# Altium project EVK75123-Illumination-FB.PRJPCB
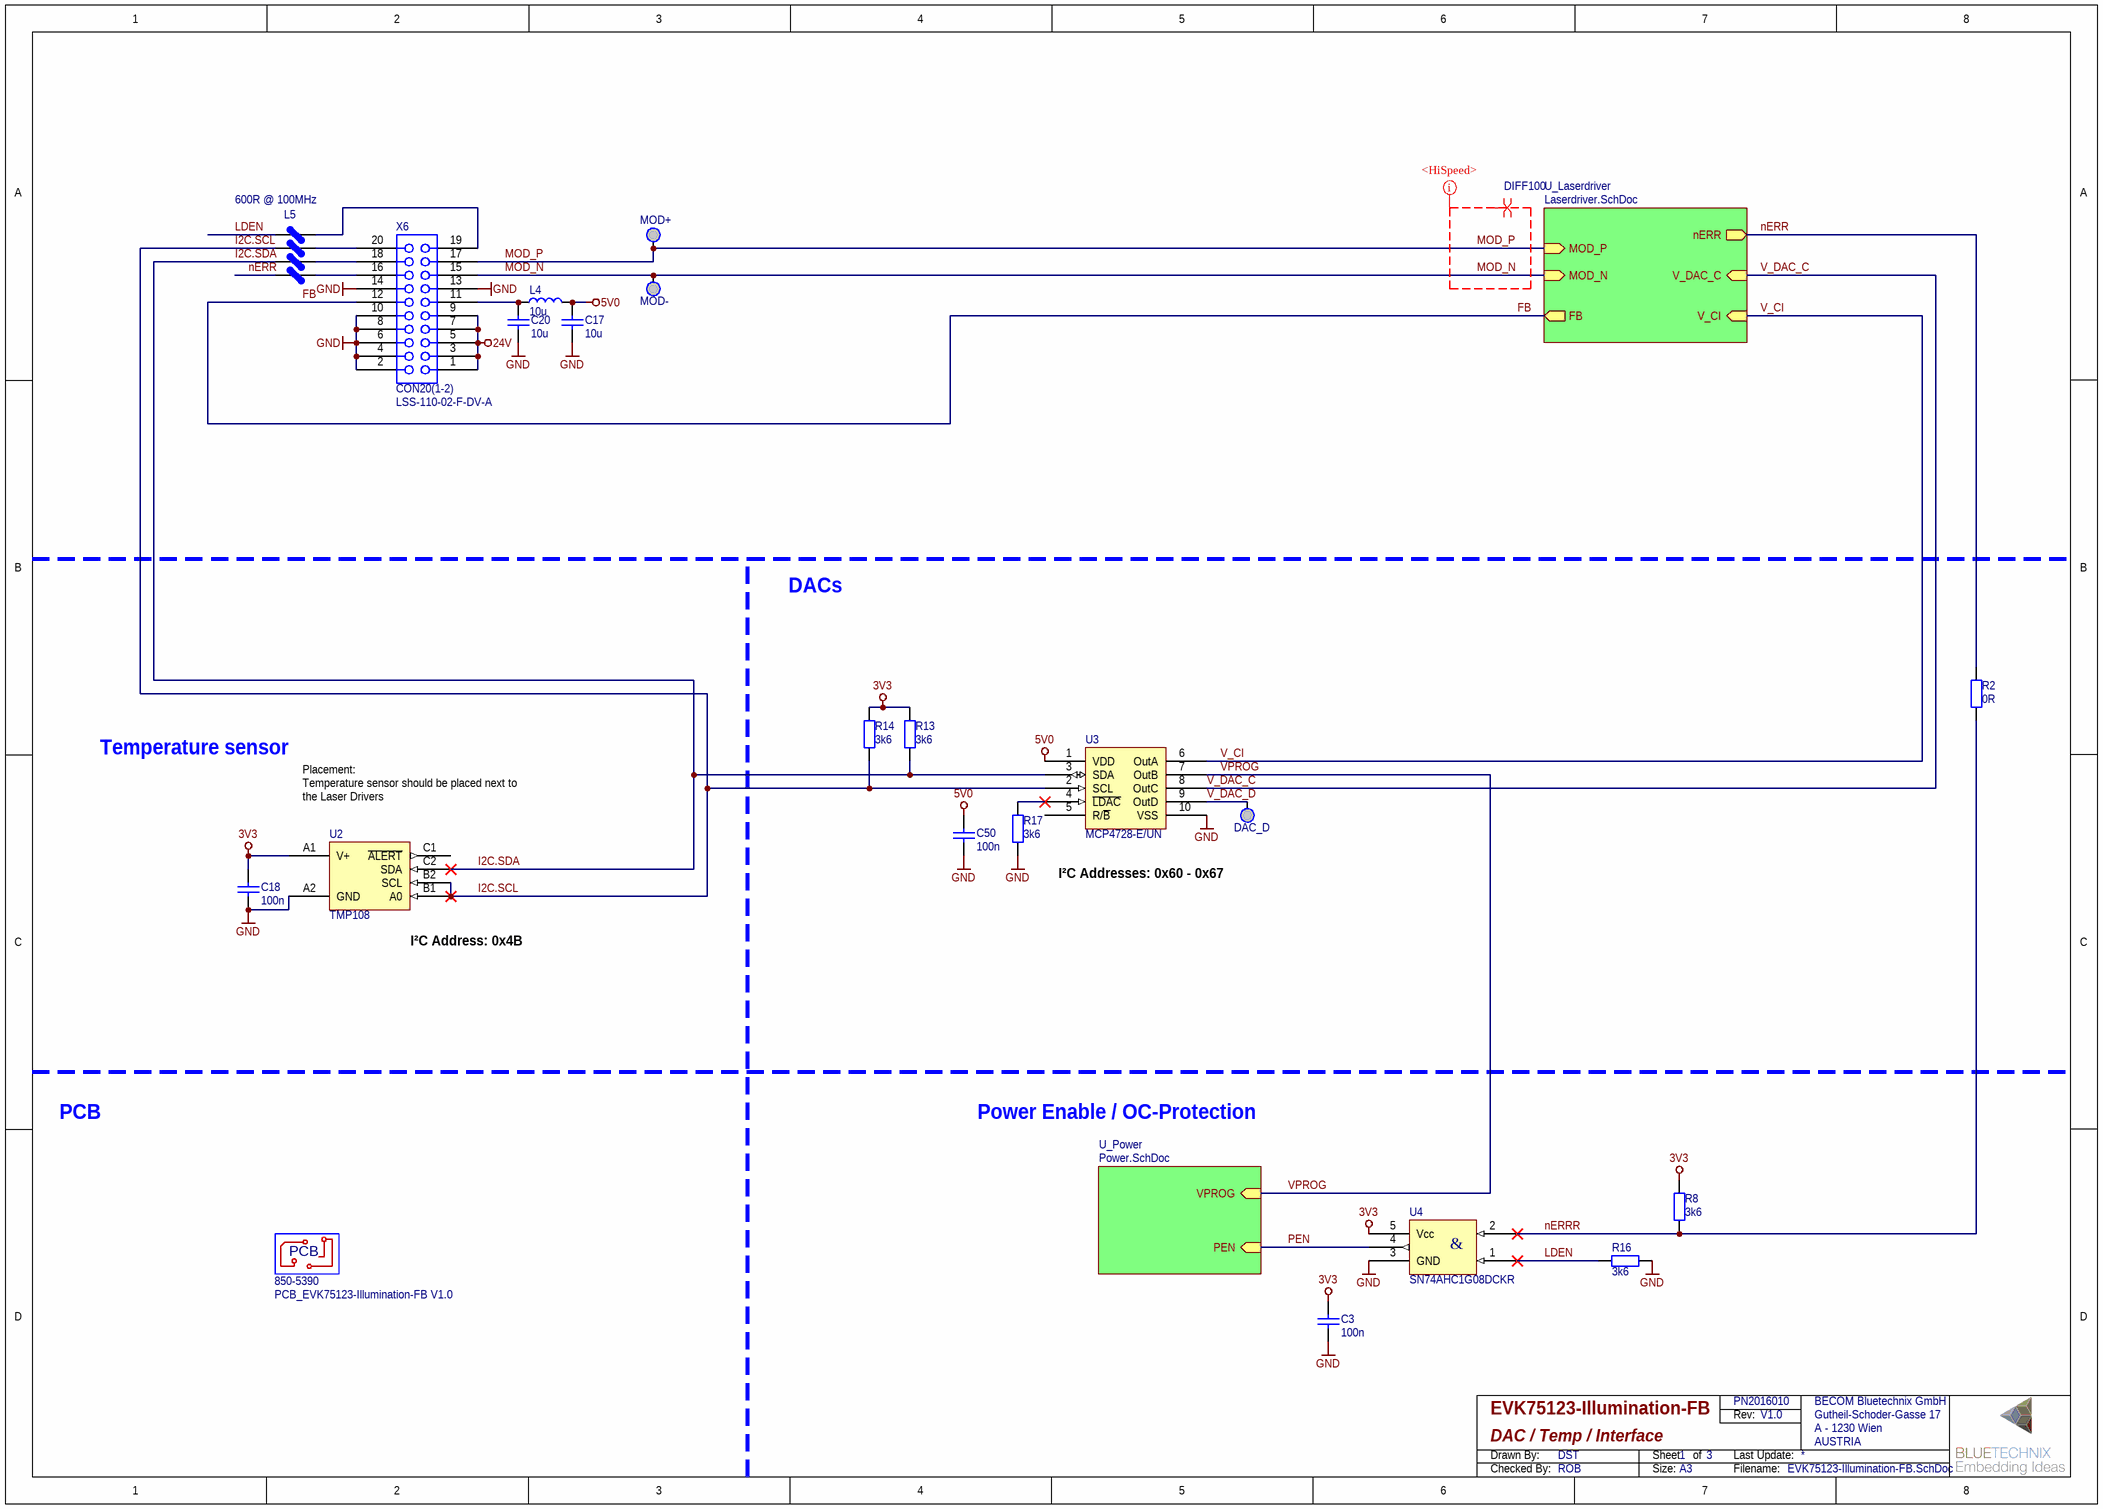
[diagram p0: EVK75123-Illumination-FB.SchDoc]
prj_name: EVK75123-Illumination-FB; prj_num: PN2016010; prj_vers: V1.0
3 sheets, 109 parts. Net scope: hierarchical (ports join the sheet entries above them; power ports are global).
Board file: EVK75123-Illumination-FB.PcbDoc
Sheets:
  EVK75123-Illumination-FB.SchDoc
    U_Power = Power.SchDoc
    U_Laserdriver = Laserdriver.SchDoc

## Sheet EVK75123-Illumination-FB.SchDoc: DAC / Temp / Interface
size A3; CheckedBy: ROB; DrawnBy: DST; Organization: BECOM Bluetechnix GmbH; Address1: Gutheil-Schoder-Gasse 17; Address2: A - 1230 Wien; Address3: AUSTRIA; DocumentNumber: 1; Revision: V1.0; SheetNumber: 1; SheetTotal: 3

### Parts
C3  C: 100n  [0402]  (hidden comment: Capacitor non-polarized)
C17  C: 10u  [0805]  (hidden comment: Capacitor non-polarized)
C18  C: 100n  [0402]  (hidden comment: Capacitor non-polarized)
C20  C: 10u  [0805]  (hidden comment: Capacitor non-polarized)
C50  C: 100n  [0402]  (hidden comment: Capacitor non-polarized)
DAC_D  Test Pad  [PAD_1mm_SMD]  (value not drawn)  (no BOM)
L4  L: 10u  [1210]  (hidden comment: Inductor)
L5  Z: 600R @ 100MHz  [1206_FB-array]  (hidden comment: Ferrite)
MOD+  Test Pad  [PAD_1mm_SMD]  (value not drawn)  (no BOM)
MOD-  Test Pad  [PAD_1mm_SMD]  (value not drawn)  (no BOM)
PCB  850-5390  [PCB]
R2  R: 0R  [0805]  (hidden comment: Resistor)
R8  R: 3k6  [0402]  (hidden comment: Resistor)
R13  R: 3k6  [0402]  (hidden comment: Resistor)
R14  R: 3k6  [0402]  (hidden comment: Resistor)
R16  R: 3k6  [0402]  (hidden comment: Resistor)
R17  R: 3k6  [0402]  (hidden comment: Resistor)
U2  TMP108  [BGA6-0.4-0.25-1.2x0.8]
U3  NAME: MCP4728-E/UN  [MSOP10-0.5-5]  (hidden comment: MCP4728)
U4  NAME: SN74AHC1G08DCKR  [SOT353-0.65--2.6]  (hidden comment: Single-Gate Dual-Input AND-Logic-Gate)
X6  CON20(1-2)  NAME: LSS-110-02-F-DV-A  [SAM-LSS-110-02-F-DV-A]

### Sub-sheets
U_Laserdriver = Laserdriver.SchDoc: MOD_P (in), MOD_N (in), nERR (out), V_CI (in), V_DAC_C (in), FB (out)
U_Power = Power.SchDoc: PEN (in), VPROG (in)

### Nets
3V3: C3.1 C18.2 R8.2 R13.2 R14.2 U2.A1(V+) U4.5(Vcc)
5V0: C17.2 C50.2 L4.2 U3.1(VDD)
24V: X6.1 X6.3 X6.5 X6.7 X6.9
GND: C3.2 C17.1 C18.1 C20.1 C50.1 R16.2 R17.1 U2.A2(GND) U3.10(VSS) U4.3(GND) X6.2 X6.4 X6.6 X6.8 X6.10 X6.13 X6.14
FB: X6.12 ; sheet U_Laserdriver/FB
I2C.SCL: L5.3 R14.1 U2.B1(A0) U2.B2(SCL) U3.2(SCL)
I2C.SDA: L5.2 R13.1 U2.C2(SDA) U3.3(SDA)
LDEN: L5.4 R16.1 U4.1(inB)
MOD_N: MOD-.1 X6.15 ; sheet U_Laserdriver/MOD_N
MOD_P: MOD+.1 X6.17 ; sheet U_Laserdriver/MOD_P
nERR: L5.1 R2.1 ; sheet U_Laserdriver/nERR
nERRR: R2.2 R8.1 U4.2(inA)
PEN: U4.4(out) ; sheet U_Power/PEN
V_CI: U3.6(OutA) ; sheet U_Laserdriver/V_CI
V_DAC_C: U3.8(OutC) ; sheet U_Laserdriver/V_DAC_C
V_DAC_D: DAC_D.1 U3.9(OutD)
VPROG: U3.7(OutB) ; sheet U_Power/VPROG
NetC20_2: C20.2 L4.1 X6.11
NetL5_5: L5.5 X6.19
NetL5_6: L5.6 X6.20
NetL5_7: L5.7 X6.18
NetL5_8: L5.8 X6.16
NetR17_2: R17.2 U3.4(~{LDAC})

Not connected (* = marked no-connect by the designer): U2 C1(~{ALERT}); U3 5(R/~{B})

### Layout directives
net class <HiSpeed>: MOD_N, MOD_P
differential pair; net class DIFF100: MOD_N, MOD_P

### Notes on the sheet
- DACs
- Temperature sensor
- Placement:
  Temperature sensor should be placed next to the Laser Drivers
- I²C Addresses: 0x60 - 0x67
- I²C Address: 0x4B
- PCB
- Power Enable / OC-Protection

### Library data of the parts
C3 = 54C877D5-E705-4C14-AD3D-8F4F7B57D597: C-0402-100n-16V-10%; Manufacturer: Murata; ArticleNumber: 710-0138; NAME: GRM155R71C104KA88D; Inventory Storage Name: LBaut; Inventory Storage Section: C3; Sachgruppe: Keramikscheiben; SachgruppeCode: C_KERAMIK; IsReviewed: 1; Dielektrikum: X7R; Montage: SMD; T-bereich: -55°C : +125°C; T_Koeffizient: ± 15%; Toleranz: 10%; U: 16V; InternalPrice: 0,011693; InternalStock: 600684
C17 C20 = 47BE2105-E645-4B7D-88B5-189FA600BE5F: C-0805-10u-10V-10%; Manufacturer: PhyComp; ArticleNumber: 710-0019; NAME: CC0805KKX5R6BB106; Inventory Storage Name: LBaut; Inventory Storage Section: C1; Sachgruppe: C_KERAMIK; SachgruppeCode: Keramikscheiben; IsReviewed: 1; InternalPrice: 0,285138; InternalStock: 500; U: 10V; Toleranz: 10%; Dielektrikum: X5R; T_Koeffizient: ± 15%; T-bereich: -55°C : +85°C; Montage: SMD
C18 = 54C877D5-E705-4C14-AD3D-8F4F7B57D597: C-0402-100n-16V-10%; Manufacturer: Murata; ArticleNumber: 710-0138; NAME: GRM155R71C104KA88D; Inventory Storage Name: LBaut; Inventory Storage Section: C3; Sachgruppe: Keramikscheiben; SachgruppeCode: C_KERAMIK; IsReviewed: 1; U: 16V; Toleranz: 10%; Dielektrikum: X7R; T_Koeffizient: ± 15%; T-bereich: -55°C : +125°C; Montage: SMD; InternalPrice: 0,013001; InternalStock: 607228
C50 = 54C877D5-E705-4C14-AD3D-8F4F7B57D597: C-0402-100n-16V-10%; Manufacturer: Murata; ArticleNumber: 710-0138; NAME: GRM155R71C104KA88D; Inventory Storage Name: LBaut; Inventory Storage Section: C3; Sachgruppe: Keramikscheiben; SachgruppeCode: C_KERAMIK; IsReviewed: 1; Dielektrikum: X7R; Montage: SMD; T-bereich: -55°C : +125°C; T_Koeffizient: ± 15%; Toleranz: 10%; U: 16V; InternalPrice: 0,013001; InternalStock: 607228
DAC_D MOD+ MOD- = D58E77CC-74E0-4972-9B60-0D1F1EE06ED8: Test Pad 1mm; Manufacturer: Bluetechnix; ArticleNumber: 810-0021; Inventory Storage Name: L2; SachgruppeCode: SV_TEST; IsReviewed: 1; InternalPrice: 0; Montage: THD
L4 = 5A39A3C7-8FFF-4AB6-80A4-55595FBEE935: L-1210-10u-450mA; Manufacturer: Murata; ArticleNumber: 770-0040; NAME: LQH32CN100K33L; Inventory Storage Name: LBaut; Inventory Storage Section: I4; Sachgruppe: IN_SPEICHERDROSSELN; SachgruppeCode: Speicherdrosseln; IsReviewed: 1; InternalPrice: 0,28; InternalStock: 400; Core: Ferrit; I: 0.45A; Toleranz: 10%; R_dc: 0R3; Q: 35; f_res: 26MHz; Schirm: n; Montage: SMD; T-bereich: -25°C : +85°C
L5 = 17bc767e-4081-41c9-96a1-8705f6a55660: F-1206array-600Z-100mA; Manufacturer: Taiyo Yuden; ArticleNumber: 740-0005; NAME: BK32164M601-T; Inventory Storage Name: LBaut; Inventory Storage Section: L1; Sachgruppe: FI_FERRITPERLEN; SachgruppeCode: Ferritperlen; IsReviewed: 1; InternalPrice: 0,09; InternalStock: 188; Wege: 4; R_dc: 0R6; Bandbreite: 250R @ 1GHz; Frequenz: 220MHz; I_max: 100mA; Bauform: 1206-array; Montage: SMD; T-bereich: -55°C : +125°C
PCB = 5ec15bad-9016-406e-8801-bfda4c5ae292: PCB_EVK75123-Illumination-FB V1.0; Manufacturer: Bluetechnix; Inventory Storage Name: L2; Sachgruppe: PCB_EXTPROJEKT; SachgruppeCode: externe Projekte; IsReviewed: 0; Kunde: Melexis
R2 = 96878DCE-2E24-48BD-A958-A9B2669E8EA5: R-0805-0R-5%; Manufacturer: YAGEO; ArticleNumber: 780-0259; NAME: RC0805JR-070RL; Inventory Storage Name: LBaut; Inventory Storage Section: R6; Sachgruppe: R_DICKSCHICHT; SachgruppeCode: Dickschicht; IsReviewed: 1; InternalPrice: 0,002857; InternalStock: 9206; P: 0.125W; Toleranz: 5%; T_Koeffizient: ± 250ppm/°C; Montage: SMD
R8 R13 R14 R16 R17 = 87ff11f6-a19c-4fd3-a86d-d729e9959c04: R-0402-3k6-1%; Manufacturer: MULTICOMP; ArticleNumber: 780-0477; NAME: MC 0.0625W 0402 1% 3K6; Inventory Storage Name: LBaut; Sachgruppe: Dickschicht; SachgruppeCode: R_DICKSCHICHT; IsReviewed: 1; InternalPrice: 0,040357; InternalStock: 256; P: 0.0625W; Toleranz: 1%; T_Koeffizient: ± 100ppm/°C; Montage: SMD; T-bereich: -55°C : +155°C; Inventory Storage Section: R10
U2 = 1756c951-2cf8-4c64-a988-e546f59afa21: ±1°C Accurate 12bit Digital Temperature Sensor; Manufacturer: Texas Instruments; ArticleNumber: 730-0256; Inventory Storage Name: L2; Sachgruppe: SENSOREN; IsReviewed: 0; Interface: SMBus/I2C; Messbereich: -40°C : +125°C; U: 1.4V : 3.6V; Bauform: WCSP6 (DSBGA-6); Montage: SMD; Kommentar: I²C: 0x70; PM: TA
U3 = 7021478d-2d84-431d-b8be-32d6dfcf2c4d: 12-Bit Digital-to-Analog Converter with EEPROM Memory; Manufacturer: Microchip; ArticleNumber: 700-1100; Inventory Storage Name: L2; Sachgruppe: IC_DATEN_SIGNALWANDLER; SachgruppeCode: Daten-/Signalwandler; IsReviewed: 0; Typ: DAC; Outputs: 4; Interface: I²C; U_IO: 2.7V : 5.5V; Aufloesung: 12bit; f_abtast: 166kHz; T-bereich: -40°C : +125°C; Bauform: MSOP10; Montage: SMD; topmark: 4728UN
U4 = B349E2D1-8349-4508-822A-E73FFBEB3634: 74AHC1G08; Manufacturer: Texas Instruments; ArticleNumber: 700-0623; Inventory Storage Name: LBaut; Inventory Storage Section: U20; Sachgruppe: Logic; SachgruppeCode: IC_LOGIC; IsReviewed: 1; InternalPrice: 0,06506; InternalStock: 172; Logik-Gruppe (NOR): AND; Logik-Typ (7402): 7408; Serie (HCT): AHC; Inputs: 2; Trigger: state; Out-Typ: TTL; t_t: 7ns; U: 2.0V : 5.5V; T-bereich: -40°C : +85°C; Bauform: SOT353-5; Montage: SMD; topmark: AE_
X6 = 379f8e5c-a288-4eeb-8f71-ca0e0501eadd: High speed hermaphrodotoc strip; Manufacturer: Samtec; ArticleNumber: 810-0543; Inventory Storage Name: LBaut; Inventory Storage Section: X23; Sachgruppe: Mezzanin; SachgruppeCode: SV_MEZZANIN; IsReviewed: 1; InternalPrice: 0,853333; InternalStock: 60; Typ: B2B; Pole: 20; Gender: h; Winkel: 180°; Reihen: 2; Pitch: 0.635mm; I_max: 1.7A; Montage: SMD; Kommentar: hermaphroditic 7.49mm; T-bereich: -55°C : +125°C

## Sheet Power.SchDoc: Power
size A4; CheckedBy: ROB; DrawnBy: DST; Organization: BECOM Bluetechnix GmbH; Address1: Gutheil-Schoder-Gasse 17; Address2: A - 1230 Wien; Address3: AUSTRIA; DocumentNumber: 3; Revision: V1.0; SheetNumber: 3; SheetTotal: 3
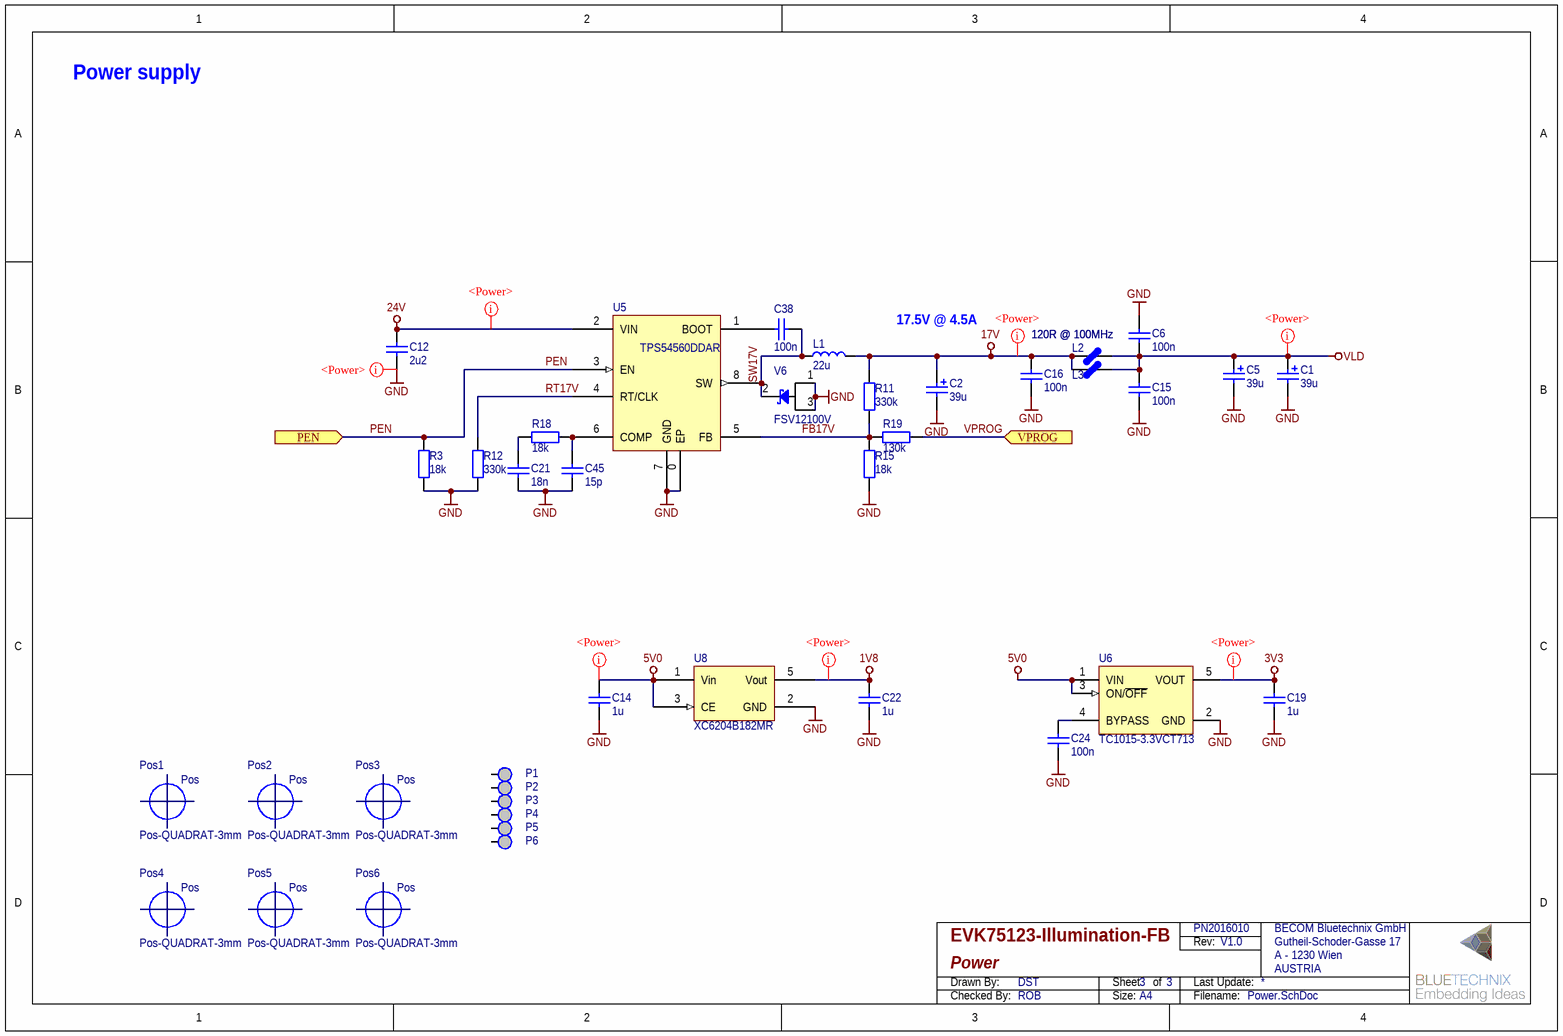
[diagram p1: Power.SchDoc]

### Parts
C1  C: 39u  [ELKO_SMD-8x7]  (hidden comment: Polarized Capicator)
C2  C: 39u  [ELKO_SMD-8x7]  (hidden comment: Polarized Capicator)
C5  C: 39u  [ELKO_SMD-8x7]  (hidden comment: Polarized Capicator)
C6  C: 100n  [1206]  (hidden comment: Capacitor non-polarized)
C12  C: 2u2  [1210]  (hidden comment: Capacitor non-polarized)
C14  C: 1u  [0603]  (hidden comment: Capacitor non-polarized)
C15  C: 100n  [1206]  (hidden comment: Capacitor non-polarized)
C16  C: 100n  [0603]  (hidden comment: Capacitor non-polarized)
C19  C: 1u  [0603]  (hidden comment: Capacitor non-polarized)
C21  C: 18n  [0402]  (hidden comment: Capacitor non-polarized)
C22  C: 1u  [0603]  (hidden comment: Capacitor non-polarized)
C24  C: 100n  [0603]  (hidden comment: Capacitor non-polarized)
C38  C: 100n  [0603]  (hidden comment: Capacitor non-polarized)
C45  C: 15p  [0402]  (hidden comment: Capacitor non-polarized)
L1  L: 22u  [VIS-IHLP-6767DZ]  (hidden comment: Inductor)
L2  Z: 120R @ 100MHz  [0805]  (hidden comment: Ferrite)
L3  Z: 120R @ 100MHz  [0805]  (hidden comment: Ferrite)
P1  Test Pad  [PAD_M2-5x5]  (value not drawn)  (no BOM)
P2  Test Pad  [PAD_M2-5x5]  (value not drawn)  (no BOM)
P3  Test Pad  [PAD_M2-5x5]  (value not drawn)  (no BOM)
P4  Test Pad  [PAD_M2-5x5]  (value not drawn)  (no BOM)
P5  Test Pad  [PAD_M2-5x5]  (value not drawn)  (no BOM)
P6  Test Pad  [PAD_M2-5x5]  (value not drawn)  (no BOM)
Pos1  Position  [Pos-QUADRAT]  (value not drawn)
Pos2  Position  [Pos-QUADRAT]  (value not drawn)
Pos3  Position  [Pos-QUADRAT]  (value not drawn)
Pos4  Position  [Pos-QUADRAT]  (value not drawn)
Pos5  Position  [Pos-QUADRAT]  (value not drawn)
Pos6  Position  [Pos-QUADRAT]  (value not drawn)
R3  R: 18k  [0402]  (hidden comment: Resistor)
R11  R: 330k  [0402]  (hidden comment: Resistor)
R12  R: 330k  [0402]  (hidden comment: Resistor)
R15  R: 18k  [0402]  (hidden comment: Resistor)
R18  R: 18k  [0402]  (hidden comment: Resistor)
R19  R: 130k  [0402]  (hidden comment: Resistor)
U5  NAME: TPS54560DDAR  [PSO8-1.27-7.3]  (hidden comment: TPS54061)
U6  NAME: TC1015-3.3VCT713  [SOT23-5-0.95--3.6]  (hidden comment: LP2985)
U8  NAME: XC6204B182MR  [SOT23-5-0.95--3.6]  (hidden comment: High-Speed LDO Voltage-Regulator)
V6  NAME: FSV12100V  [TO-277-3]  (hidden comment: Default Diode)

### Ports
PEN (in), VPROG (in)

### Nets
1V8: C22.2 U8.5(Vout)
3V3: C19.2 U6.5(VOUT)
5V0: C14.2 U6.1(VIN) U6.3(ON/~{OFF}) U8.1(Vin) U8.3(CE)
17V: C2.1 C16.1 L1.2 L2.1 L3.1 R11.1
24V: C12.2 U5.2(VIN)
GND: C1.2 C2.2 C5.2 C6.2 C12.1 C14.1 C15.1 C16.2 C19.1 C21.1 C22.1 C24.2 C45.1 R3.1 R12.2 R15.1 U5.0(EP) U5.7(GND) U6.2(GND) U8.2(GND) V6.1(A) V6.3(A)
VLD: C1.1 C5.1 C6.1 C15.2 L2.2 L3.2
FB17V: R11.2 R15.2 R19.1 U5.5(FB)
PEN: R3.2 U5.3(EN) ; port PEN
RT17V: R12.1 U5.4(RT/CLK)
SW17V: C38.1 L1.1 U5.8(SW) V6.2(K)
VPROG: R19.2 ; port VPROG
NetC21_2: C21.2 R18.2
NetC24_1: C24.1 U6.4(BYPASS)
NetC38_2: C38.2 U5.1(BOOT)
NetC45_2: C45.2 R18.1 U5.6(COMP)

Not connected (* = marked no-connect by the designer): P1 1; P2 1; P3 1; P4 1; P5 1; P6 1

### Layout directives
net class <Power>: 1V8, 3V3, 5V0, 17V, 24V, GND, VLD

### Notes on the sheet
- Power supply
- 17.5V @ 4.5A

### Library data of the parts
C1 C2 C5 = 44276342-0de9-47a7-a7a6-11334c4a2d95: C-39u-35V-20%-30mR; Manufacturer: Panasonic; ArticleNumber: 710-0385; NAME: 35SVPF39M; Inventory Storage Name: LBaut; Inventory Storage Section: C7; Sachgruppe: C_ALUMINIUM_ELKO; SachgruppeCode: Aluminium Elektrolyt; IsReviewed: 0; InternalPrice: 0,417272; InternalStock: 8; U: 35V; Toleranz: 20%; ESR: 30mR; Z: 30mR @ 100kHz; T-bereich: -55°C : +105°C; Lebensdauer: 5000h @ 105°C; Bauform: 8.3x8.3x6.9; Montage: SMD; Kommentar: Irip=2.8A
C6 C15 = 6574bd8d-1f7f-4017-8c13-fc1ff6c564f2: C-1206-100n-50V-5%; Manufacturer: TDK; ArticleNumber: 710-0354; NAME: CGA5L2C0G1H104J160AA; Inventory Storage Name: L2; Sachgruppe: C_KERAMIK; SachgruppeCode: Keramikscheiben; IsReviewed: 1; InternalPrice: 0; InternalStock: 12; U: 50V; Toleranz: 5%; Dielektrikum: C0G; T-bereich: -55°C : +125°C; Montage: SMD
C12 = c11633e3-883f-4ea1-bab5-305a930c1712: C-1210-2u2-100V-X7R; Manufacturer: Kemet; ArticleNumber: 710-0311; NAME: C1210C225K1RACTU; Inventory Storage Name: LBaut; Inventory Storage Section: C6; Sachgruppe: C_KERAMIK; SachgruppeCode: Keramikscheiben; IsReviewed: 1; InternalPrice: 0,24625; InternalStock: 20; U: 100V; Toleranz: 10%; Dielektrikum: X7R; T_Koeffizient: ± 15%; T-bereich: -55°C : +125°C; Montage: SMD
C14 C19 C22 = 62C539F0-6F12-4C64-8973-B77ABBA35E0D: C-0603-1u-25V-10%; Manufacturer: Kemet; ArticleNumber: 710-0184; NAME: C0603C105K3PACTU; Inventory Storage Name: LBaut; Inventory Storage Section: C4; Sachgruppe: C_KERAMIK; SachgruppeCode: Keramikscheiben; IsReviewed: 1; InternalPrice: 0,009729; InternalStock: 756; U: 25V; Toleranz: 10%; Dielektrikum: X5R; T_Koeffizient: ± 15%; T-bereich: -55°C : +85°C; Montage: SMD
C16 C24 C38 = F4F417EB-80BB-43BD-9294-E69FEC10CC02: C-0603-100n-50V-10%; Manufacturer: MULTICOMP; ArticleNumber: 710-0283; NAME: MCCA000255; Inventory Storage Name: LBaut; Inventory Storage Section: C6; Sachgruppe: Keramikscheiben; SachgruppeCode: C_KERAMIK; IsReviewed: 1; InternalPrice: 0,01; InternalStock: 1912; U: 50V; Toleranz: 10%; Dielektrikum: X7R; T_Koeffizient: ± 15%; T-bereich: -55°C : +125°C; Montage: SMD
C21 = 0D03DA8E-6E9D-48FA-B2D5-DDC88D2A4CF2: C-0402-18n-16V-10%; Manufacturer: AVX; ArticleNumber: 710-0219; NAME: 0402YC183KAT2A; Inventory Storage Name: LBaut; Inventory Storage Section: C5; Sachgruppe: C_KERAMIK; SachgruppeCode: Keramikscheiben; IsReviewed: 1; InternalPrice: 0; U: 16V; Toleranz: 10%; Dielektrikum: X7R; T_Koeffizient: ±15%; T-bereich: -55°C : +125°C; Montage: SMD
C45 = 11FE33DF-B8B2-497C-ADE2-798944BCF4BE: C-0402-15p-50V-5%; Manufacturer: PhyComp; ArticleNumber: 710-0115; NAME: CC0402JRNPO9BN150; Inventory Storage Name: LBaut; Inventory Storage Section: C3; Sachgruppe: C_KERAMIK; SachgruppeCode: Keramikscheiben; IsReviewed: 1; InternalPrice: 0,009; InternalStock: 288; U: 50V; Toleranz: 5%; Dielektrikum: C0G; T_Koeffizient: ± 15%; T-bereich: -55°C : +125°C; Montage: SMD
L1 = c927bdf3-e195-4335-ae34-2dcccbc64859: L-VIS-IHLP-6767-22u-6.2A-20%; Manufacturer: Vishay; ArticleNumber: 770-0190; NAME: IHLP6767DZER220M11; Inventory Storage Name: L2; Sachgruppe: IN_SPEICHERDROSSELN; SachgruppeCode: Speicherdrosseln; IsReviewed: 0; I: 7.2A; I_sat: 6.2A; Toleranz: 20%; R_dc: 0R043; f_res: 5MHz; Schirm: y; Bauform: 17 x 17 x 4 mm; Montage: SMD; T-bereich: -55°C : +155°C
L2 L3 = 4558f3ef-a2ca-4732-a97e-33e36c5aad12: F-0805-120Z-5A; Manufacturer: MEC MARCOM; ArticleNumber: 740-0008; NAME: MLB-201209-0120PU; Inventory Storage Name: LBaut; Inventory Storage Section: L2; Sachgruppe: FI_FERRITPERLEN; SachgruppeCode: Ferritperlen; IsReviewed: 1; InternalPrice: 0,068522; InternalStock: 84; R_dc: 0R02; Bandbreite: 110R @ 1GHz; Frequenz: 300MHz; I_max: 5A; Montage: SMD; T-bereich: -55°C : +125°C
P1-P6 = d95d2f47-965b-47b2-ac00-e8d5b9325de3: M2 Mounting Hole 5x5; Manufacturer: Bluetechnix; ArticleNumber: 810-0545; Inventory Storage Name: L2; SachgruppeCode: SV_TEST; IsReviewed: 1; InternalPrice: 0; Typ: Mount Hole
Pos1-Pos6 = A97550DC-E5EA-465D-9168-34E3565B8720: Pos-QUADRAT-3mm; Manufacturer: Bluetechnix; MountOption: DNP; ArticleNumber: 880-0007; Inventory Storage Name: L2; Sachgruppe: PCB-Symbole; SachgruppeCode: DIV_SYMBOLE; IsReviewed: 1; Groesse: 3mm; InternalPrice: 0
R3 R15 = A4A7BB00-465D-4C1E-8319-4836672F5686: R-0402-18k-1%; Manufacturer: YAGEO; ArticleNumber: 780-0108; NAME: RC0402FR-0718KL; Inventory Storage Name: LBaut; Inventory Storage Section: R3; Sachgruppe: R_DICKSCHICHT; SachgruppeCode: Dickschicht; IsReviewed: 1; InternalPrice: 0,009565; InternalStock: 808; P: 0.063W; Toleranz: 1%; T_Koeffizient: ± 250ppm/°C; Montage: SMD; T-bereich: -55°C : +155°C
R11 R12 = 0499915E-9BF4-4C7F-8B08-D182950F3B89: R-0402-330k-1%; Manufacturer: YAGEO; ArticleNumber: 780-0326; NAME: RC0402FR-07330KL; Inventory Storage Name: LBaut; Inventory Storage Section: R7; Sachgruppe: R_DICKSCHICHT; SachgruppeCode: Dickschicht; IsReviewed: 1; InternalPrice: 0,01625; InternalStock: 86; P: 0.063W; Toleranz: 1%; T_Koeffizient: ± 250ppm/°C; Montage: SMD; T-bereich: -55°C : +155°C
R18 = A4A7BB00-465D-4C1E-8319-4836672F5686: R-0402-18k-1%; Manufacturer: YAGEO; ArticleNumber: 780-0108; NAME: RC0402FR-0718KL; Inventory Storage Name: LBaut; Inventory Storage Section: R3; Sachgruppe: R_DICKSCHICHT; SachgruppeCode: Dickschicht; IsReviewed: 1; InternalPrice: 0,00923; InternalStock: 972; P: 0.063W; Toleranz: 1%; T_Koeffizient: ± 250ppm/°C; Montage: SMD; T-bereich: -55°C : +155°C
R19 = 57b0607b-283e-4831-8b97-1b038861c010: R-0402-130k-1%; Manufacturer: Multcomp; ArticleNumber: 780-0509; NAME: MCMR04X1303FTL; Inventory Storage Name: LBaut; Inventory Storage Section: R11; Sachgruppe: R_DICKSCHICHT; SachgruppeCode: Dickschicht; IsReviewed: 1; InternalPrice: 0,001481; InternalStock: 122; P: 0.063W; Toleranz: 1%; T_Koeffizient: ± 100ppm/°C; Montage: SMD; T-bereich: -55°C : +125°C
U5 = 83e8cd34-1e26-4937-9357-3a852f02699a: 4.5 V to 60 V Input, 5 A, Step Down DC-DC Converter with Eco-mode; Manufacturer: Texas Instruments; ArticleNumber: 700-1098; Inventory Storage Name: LBaut; Inventory Storage Section: U48; Sachgruppe: PM_BUCK; SachgruppeCode: Buck; IsReviewed: 0; InternalPrice: 2,225; InternalStock: 2; U_in(max): 60V; U_in(min): 4.5V; U_out(max): 58.8V; U_out(min): 0.8V; fix_var: var; I_out: 5A; T-bereich: -40°C : +150°C; Bauform: HSOP8; Montage: SMD; Frequenz: 100kHz : 2.5MHz
U6 = 595174d6-4f0f-4a85-858e-941119242838: 3.3V, Micropower 100 mA Low-Noise Ultra Low-Dropout Regulator; Manufacturer: Microchip Technology; ArticleNumber: 700-0834; Inventory Storage Name: LBaut; Inventory Storage Section: U31; Sachgruppe: PM_LINEAR; SachgruppeCode: Linear; IsReviewed: 1; InternalPrice: 0,255; InternalStock: 136; Typ: 3V3 LDO; U_in(max): 6V; U_in(min): 2.7V; fix_var: fix; I_out: 100mA; U_drop_out: 180mV; T-bereich: -40°C : +125°C; Bauform: SOT235; Montage: SMD; topmark: TC1015
U8 = 70773BAF-7633-4D88-81D5-082B1EC5F3A9: XC6204B-1V8; Manufacturer: Torex; ArticleNumber: 700-0025; Inventory Storage Name: LBaut; Inventory Storage Section: U2; Sachgruppe: PM_LINEAR; SachgruppeCode: Linear; IsReviewed: 1; InternalPrice: 0,394782; InternalStock: 182; U_in(max): 10V; U_in(min): 2.8V; U_out(max): 1.8V; fix_var: fix; I_out: 150mA; U_drop_out: 200mV; T-bereich: -40°C : 85°C; Bauform: SOT23-5; Montage: SMD
V6 = a2494603-b754-4332-b2d6-676b3f1482f6: 12A, 100V Ultra-Low Vf Schottky Rectifier; Manufacturer: Fairchild; ArticleNumber: 730-0269; Inventory Storage Name: LBaut; Sachgruppe: SE_SCHOTTKY; IsReviewed: 1; U_f: 483mV @ 5A, 25°C; I_f(max): 220A; I_r: 22.5uA; t_rr: 27.33ns; C_@_U_r_f: 1124pF @ 4V, 1MHz; Montage: SMD; T-bereich: -55°C : +150°C; InternalPrice: 0,18; InternalStock: 22; Inventory Storage Section: V19

## Sheet Laserdriver.SchDoc: VCSEL-driver / Feedback
size A4; CheckedBy: ROB; DrawnBy: DST; Organization: BECOM Bluetechnix GmbH; Address1: Gutheil-Schoder-Gasse 17; Address2: A - 1230 Wien; Address3: AUSTRIA; DocumentNumber: 2; Revision: V1.0; SheetNumber: 2; SheetTotal: 3
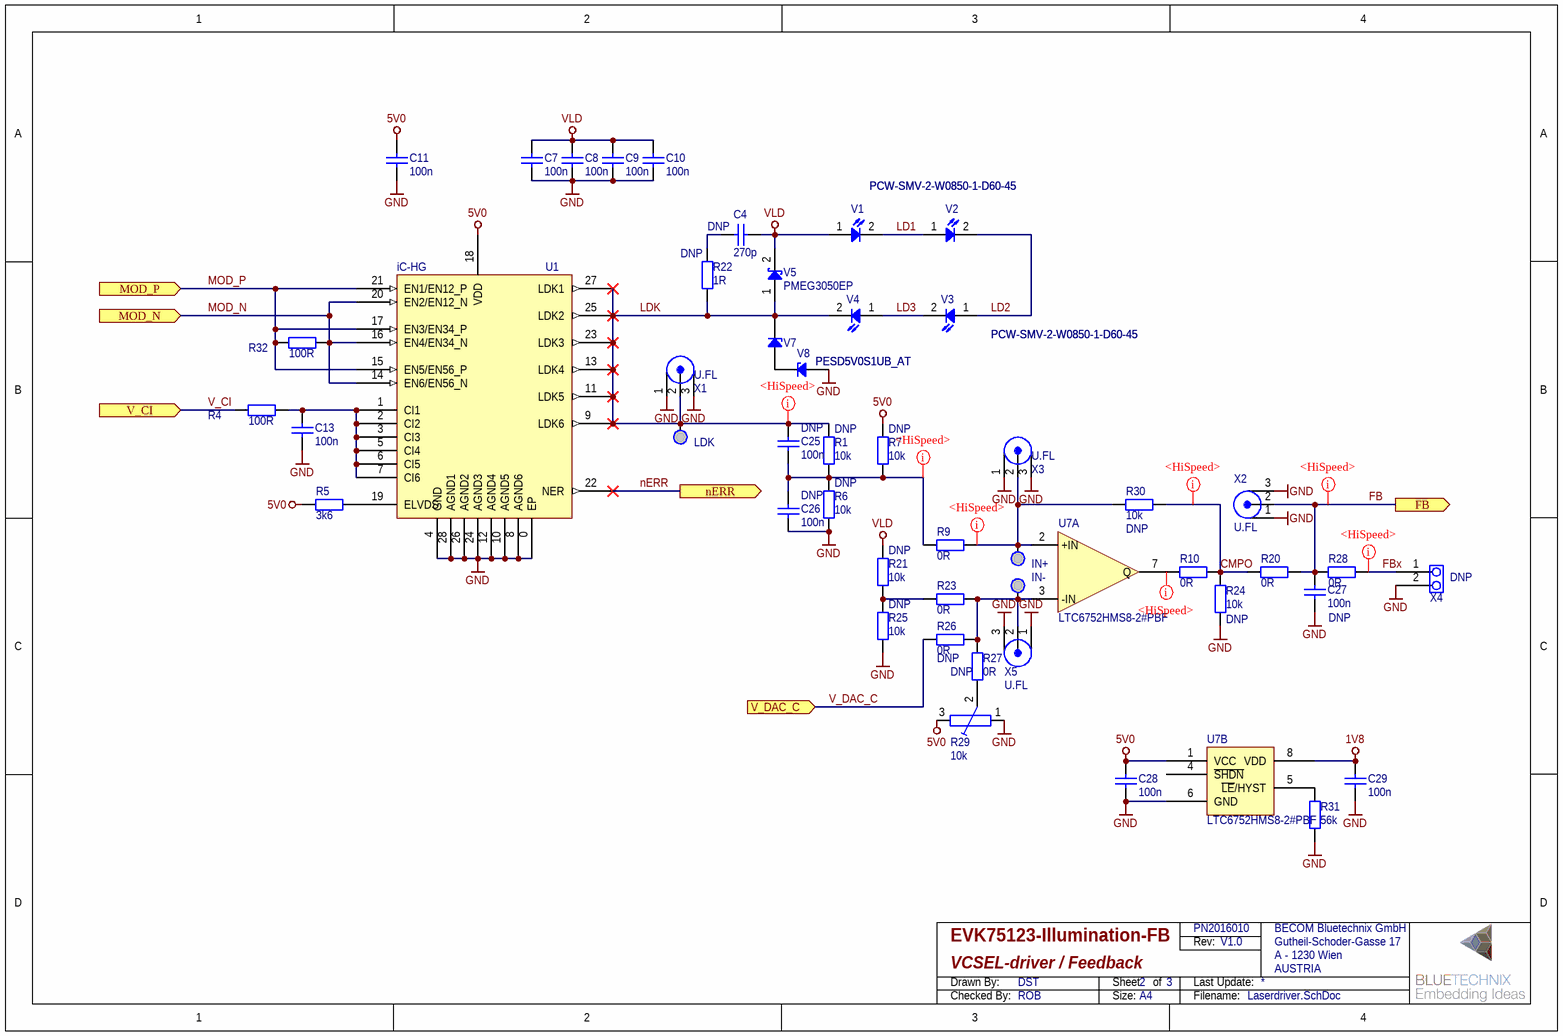
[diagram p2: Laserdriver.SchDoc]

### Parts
C4  C: 270p  MountOption: DNP  [0402]  (hidden comment: Capacitor non-polarized)
C7  C: 100n  [1206]  (hidden comment: Capacitor non-polarized)
C8  C: 100n  [1206]  (hidden comment: Capacitor non-polarized)
C9  C: 100n  [1206]  (hidden comment: Capacitor non-polarized)
C10  C: 100n  [1206]  (hidden comment: Capacitor non-polarized)
C11  C: 100n  [1206]  (hidden comment: Capacitor non-polarized)
C13  C: 100n  [0402]  (hidden comment: Capacitor non-polarized)
C25  C: 100n  MountOption: DNP  [0603]  (hidden comment: Capacitor non-polarized)
C26  C: 100n  MountOption: DNP  [0603]  (hidden comment: Capacitor non-polarized)
C27  C: 100n  MountOption: DNP  [0603]  (hidden comment: Capacitor non-polarized)
C28  C: 100n  [0603]  (hidden comment: Capacitor non-polarized)
C29  C: 100n  [0603]  (hidden comment: Capacitor non-polarized)
IN+  Test Pad  [PAD_1mm_SMD]  (value not drawn)  (no BOM)
IN-  Test Pad  [PAD_1mm_SMD]  (value not drawn)  (no BOM)
LDK  Test Pad  [PAD_1mm_SMD]  (value not drawn)  (no BOM)
R1  R: 10k  MountOption: DNP  [0603]  (hidden comment: Resistor)
R4  R: 100R  [0402]  (hidden comment: Resistor)
R5  R: 3k6  [0402]  (hidden comment: Resistor)
R6  R: 10k  MountOption: DNP  [0603]  (hidden comment: Resistor)
R7  R: 10k  MountOption: DNP  [0603]  (hidden comment: Resistor)
R9  R: 0R  [0603]  (hidden comment: Resistor)
R10  R: 0R  [0603]  (hidden comment: Resistor)
R20  R: 0R  [0603]  (hidden comment: Resistor)
R21  R: 10k  MountOption: DNP  [0603]  (hidden comment: Resistor)
R22  R: 1R  MountOption: DNP  [1206]  (hidden comment: Resistor)
R23  R: 0R  [0603]  (hidden comment: Resistor)
R24  R: 10k  MountOption: DNP  [0603]  (hidden comment: Resistor)
R25  R: 10k  MountOption: DNP  [0603]  (hidden comment: Resistor)
R26  R: 0R  MountOption: DNP  [0603]  (hidden comment: Resistor)
R27  R: 0R  MountOption: DNP  [0603]  (hidden comment: Resistor)
R28  R: 0R  [0603]  (hidden comment: Resistor)
R29  R: 10k  [POZ2AN]  (hidden comment: Trimmer)
R30  R: 10k  MountOption: DNP  [0603]  (hidden comment: Resistor)
R31  R: 56k  [0603]  (hidden comment: Resistor)
R32  R: 100R  [0402]  (hidden comment: Resistor)
U1  iC-HG  [QFN28-0.5-5-0.9]
U7  NAME: LTC6752HMS8-2#PBF  [TSSOP8-0.65--5]  (hidden comment: LTC6752HMS8-2)  (parts A,B of 2)
V1  NAME: PCW-SMV-2-W0850-1-D60-45  [PCW-SMT-2]  (hidden comment: Light Emitting Diode)
V2  NAME: PCW-SMV-2-W0850-1-D60-45  [PCW-SMT-2]  (hidden comment: Light Emitting Diode)
V3  NAME: PCW-SMV-2-W0850-1-D60-45  [PCW-SMT-2]  (hidden comment: Light Emitting Diode)
V4  NAME: PCW-SMV-2-W0850-1-D60-45  [PCW-SMT-2]  (hidden comment: Light Emitting Diode)
V5  Schottky Diode  [SOD128]  (value not drawn)
V7  NAME: PESD5V0S1UB_AT  [SOD523]  (hidden comment: Z-Diode)
V8  NAME: PESD5V0S1UB_AT  [SOD523]  (hidden comment: Z-Diode)
X1  Typ: U.FL  [HIR-2-U.FL-U.FL-R-SMT]  (hidden comment: Amphenol SMA-connector right-angled)
X2  Typ: U.FL  [HIR-2-U.FL-U.FL-R-SMT]  (hidden comment: Amphenol SMA-connector right-angled)
X3  Typ: U.FL  [HIR-2-U.FL-U.FL-R-SMT]  (hidden comment: Amphenol SMA-connector right-angled)
X4  MountOption: DNP  [PADS-2-2.54]  (hidden comment: CON2(1))  (no BOM)
X5  Typ: U.FL  [HIR-2-U.FL-U.FL-R-SMT]  (hidden comment: Amphenol SMA-connector right-angled)

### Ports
FB (out), MOD_N (in), MOD_P (in), nERR (out), V_CI (in), V_DAC_C (in)

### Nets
1V8: C29.1 U7.8(VDD)
5V0: C11.2 C28.1 R5.2 R7.1 R29.3 U1.18(VDD) U7.1(VCC)
GND: C7.1 C8.1 C9.1 C10.1 C11.1 C13.1 C26.2 C27.2 C28.2 C29.2 R6.2 R24.2 R25.2 R29.1 R31.1 U1.0(EP) U1.4(GND) U1.8(AGND6) U1.10(AGND5) U1.12(AGND4) U1.24(AGND3) U1.26(AGND2) U1.28(AGND1) U7.6(GND) V8.1(A) X1.1 X1.3 X2.1 X2.3 X3.1 X3.3 X4.2 X5.1 X5.3
VLD: C4.2 C7.2 C8.2 C9.2 C10.2 R21.1 V1.1(A) V5.2(K)
CMPO: R10.2 R20.1 R24.1 R30.2
FB: C27.1 R20.2 R28.2 X2.2 ; port FB
FBx: R28.1 X4.1
LD1: V1.2(K) V2.1(A)
LD2: V2.2(K) V3.1(A)
LD3: V3.2(K) V4.1(A)
LDK: C25.1 LDK.1 R1.1 R22.1 U1.9(LDK6) U1.11(LDK5) U1.13(LDK4) U1.23(LDK3) U1.25(LDK2) U1.27(LDK1) V4.2(K) V5.1(A) V7.2(K) X1.2
MOD_N: R32.1 U1.14(EN6/EN56_N) U1.16(EN4/EN34_N) U1.20(EN2/EN12_N) ; port MOD_N
MOD_P: R32.2 U1.15(EN5/EN56_P) U1.17(EN3/EN34_P) U1.21(EN1/EN12_P) ; port MOD_P
nERR: U1.22(NER) ; port nERR
V_CI: R4.2 ; port V_CI
V_DAC_C: R26.1 ; port V_DAC_C
NetC4_1: C4.1 R22.2
NetC13_2: C13.2 R4.1 U1.1(CI1) U1.2(CI2) U1.3(CI3) U1.5(CI4) U1.6(CI5) U1.7(CI6)
NetC25_2: C25.2 C26.1 R1.2 R6.1 R7.2 R9.1
NetIN+_1: IN+.1 R9.2 R30.1 U7.2(+IN) X3.2
NetIN-_1: IN-.1 R23.2 R26.2 R27.2 U7.3(-IN) X5.2
NetR5_1: R5.1 U1.19(ELVDS)
NetR10_1: R10.1 U7.7(Q)
NetR21_2: R21.2 R23.1 R25.1
NetR27_1: R27.1 R29.2
NetR31_2: R31.2 U7.5(~{LE}/HYST)
NetV7_1: V7.1(A) V8.2(K)

Not connected (* = marked no-connect by the designer): U7 4(~{SHDN})

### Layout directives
net class <HiSpeed>: CMPO, FB, FBx, LDK, NetC25_2, NetIN+_1, NetR10_1

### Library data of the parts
C4 = 0097ADC0-227E-4059-A51E-B4508658C31A: C-0402-270p-50V-5%; Manufacturer: KEMET; ArticleNumber: 710-0179; NAME: C0402C271J5GACTU; Inventory Storage Name: LBaut; Inventory Storage Section: C4; Sachgruppe: C_KERAMIK; SachgruppeCode: Keramikscheiben; IsReviewed: 1; InternalPrice: 0; U: 50V; Toleranz: 5%; Dielektrikum: C0G; T_Koeffizient: ± 30ppm/°C; T-bereich: -55°C : +125°C; Montage: SMD
C7-C11 = 6574bd8d-1f7f-4017-8c13-fc1ff6c564f2: as C6 on sheet Power
C13 = 54C877D5-E705-4C14-AD3D-8F4F7B57D597: as C18 on sheet EVK75123-Illumination-FB
C25-C29 = F4F417EB-80BB-43BD-9294-E69FEC10CC02: as C16 on sheet Power
IN+ IN- LDK = D58E77CC-74E0-4972-9B60-0D1F1EE06ED8: as DAC_D on sheet EVK75123-Illumination-FB
R1 R6 R7 R21 R24 R25 R30 = AA0CF608-2A67-4058-8450-88B6A96542D7: R-0603-10k-1%; Manufacturer: Multicomp; ArticleNumber: 780-0205; NAME: MC 0.063W 0603 1% 10K; Inventory Storage Name: LBaut; Inventory Storage Section: R5; Sachgruppe: R_DICKSCHICHT; SachgruppeCode: Dickschicht; IsReviewed: 1; InternalPrice: 0,012374; InternalStock: 1302; P: 0.063W; Toleranz: 1%; T_Koeffizient: ±100ppm/°C; Montage: SMD; T-bereich: -55°C : +125°C
R4 R32 = 5753A1E5-EBD2-4BBF-8026-C9AE8047C4EC: R-0402-100R-1%; Manufacturer: YAGEO; ArticleNumber: 780-0309; NAME: RC0402FR-07100RL; Inventory Storage Name: LBaut; Inventory Storage Section: R7; Sachgruppe: Dickschicht; SachgruppeCode: R_DICKSCHICHT; IsReviewed: 1; InternalPrice: 0,041102; InternalStock: 2008; P: 0.063W; Toleranz: 1%; T_Koeffizient: ± 250ppm/°C; Montage: SMD; T-bereich: -55°C : +155°C
R5 = 87ff11f6-a19c-4fd3-a86d-d729e9959c04: as R8 on sheet EVK75123-Illumination-FB
R9 R10 R20 R23 R26-R28 = E495C68F-9C71-4733-8E6B-D3B3727AEEA9: R-0603-0R; Manufacturer: Multicomp; ArticleNumber: 780-0332; NAME: MC 0.063W 0603 0R; Inventory Storage Name: LBaut; Inventory Storage Section: R7; Sachgruppe: R_DICKSCHICHT; SachgruppeCode: Dickschicht; IsReviewed: 1; InternalPrice: 0,021726; InternalStock: 240; P: 0.063W; T_Koeffizient: ± 200ppm/°C; Montage: SMD; T-bereich: -55°C : +125°C
R22 = 1a6a65a5-8098-42a8-a07d-6c7b13c9a3e6: R-1206-1R-1%-0.5W; Manufacturer: Multicomp; ArticleNumber: 780-0490; NAME: MCHP06W2F100KT5E; Inventory Storage Name: LBaut; Inventory Storage Section: R10; Sachgruppe: R_DICKSCHICHT; SachgruppeCode: Dickschicht; IsReviewed: 1; InternalPrice: 0,021929; InternalStock: 570; P: 0.5W; Toleranz: 1%; T_Koeffizient: ± 200ppm/°C; Montage: SMD; T-bereich: -55°C : 155°C
R29 = 1DD80AC4-4383-45C6-B1FE-58D03BB158C7: R-Trimmer-SMD-10k-30%; Manufacturer: Murata; ArticleNumber: 780-0131; NAME: PVZ2A103C04B00; Inventory Storage Name: LBaut; Inventory Storage Section: R3; Sachgruppe: R_POTI; SachgruppeCode: Potentiometer; IsReviewed: 1; InternalPrice: 0,176111; InternalStock: 90; P: 0.05W; Serie: PVZ2; Toleranz: 30%; lin_log: lin; T_Koeffizient: ± 500ppm/°C; Montage: SMD; T-bereich: -25°C : +85°C
R31 = 35F436D8-BE29-4562-B269-D4190D404CCA: R-0603-56k-1%; Manufacturer: Multicomp; ArticleNumber: 780-0333; NAME: MC 0.063W 0603 1% 56k; Inventory Storage Name: LBaut; Inventory Storage Section: R7; Sachgruppe: R_DICKSCHICHT; SachgruppeCode: Dickschicht; IsReviewed: 1; InternalPrice: 0,009615; InternalStock: 564; P: 0.063W; Toleranz: 1%; T_Koeffizient: ± 100ppm/°C; Montage: SMD
U1 = 900fa9a9-c7df-41b9-b82b-983ec3f9771c: 3 A LASER SWITCH; Manufacturer: iC-Haus; ArticleNumber: 700-1004; Inventory Storage Name: L2; Sachgruppe: Treiber & Interface; SachgruppeCode: IC_TREIBER_INTERFACE; IsReviewed: 1; InternalPrice: 0; Typ: Laser Diode Driver; Wege: 6; Interface: TTL/LVDS; T-bereich: -40°C : +85°C; Bauform: QFN28; Montage: SMD; U: VDD=3V : 5.5V, VH=12V
U7 = c98d9747-e96e-4882-9a1f-65f891a5ac5f: 280MHz, 2.9ns Comparator Rail-to-Rail; Manufacturer: Analog Devices; ArticleNumber: 700-1157; Inventory Storage Name: L2; Sachgruppe: IC_VERSTAERKER_KOMPARATOR; SachgruppeCode: Verstärker & Komparatoren; IsReviewed: 0; Anzahl: 1; Slew_Rate: 0,92V/µs; Verstaerkung: OLG=6000; CMRR: 65dB; U_off: ±1.2mV; U: 2.45V : 5.25V, 1.71V : 3.5V; T-bereich: -40°C : +125°C; Bauform: SOT363; Montage: SMD; Kommentar: tpd = 2.9ns; topmark: LTGKW
V1-V4 = 85e564f8-3a71-4d92-9828-a8b6dfe11ab7: VCSEL Array Laser Diode; Manufacturer: Princeton Optronics; ArticleNumber: 730-0248; Inventory Storage Name: L2; Sachgruppe: SE_LED; IsReviewed: 0; Farbe: IR; Lichtstaerke: 2W CW; Winkel: 60° x 45°; U_f: 2V; I_f(nenn): 2.7A; Lambda: 850nm; I_f(max): 10A; Anzahl: 1; Montage: SMD; T-bereich: 0°C : 80°C
V5 = 39a5ee8a-d88f-425e-8062-ede2c4d3764b: PMEG3050EP; Manufacturer: NXP; ArticleNumber: 730-0176; Inventory Storage Name: LBaut; Inventory Storage Section: V15; Sachgruppe: SE_SCHOTTKY; IsReviewed: 1; InternalPrice: 0,265555; InternalStock: 156; U_f: 0.36V; U_r: 30V; I_f(nenn): 5A; I_f(max): 70A; I_r: 2.6mA; C_@_U_r_f: 260pF @ 10V; Bauform: SOD-128; Montage: SMD; T-bereich: -55°C : +150°C; topmark: A7
V7 V8 = CC9D59A8-5C7A-4322-9DFB-934945E300CD: PESD5V0S1UB - 5.0V; Manufacturer: NXP; ArticleNumber: 730-0062; Inventory Storage Name: LBaut; Inventory Storage Section: V4; Sachgruppe: PC_TVS; SachgruppeCode: TVS; IsReviewed: 1; InternalPrice: 0,2928; InternalStock: 42; Typ: TVS Diode; U_betrieb: 5V; U_brkdn: 6.8V; P: 260W; Montage: SMD; I_pp: 15A; uni_bip: uni; Bauform: SOD-523; T-bereich: -65°C : +150°C
X1-X3 X5 = C2DB380A-A97D-4691-B92E-D6F0F144D3C9: HIR-2-U.FL-U.FL-R-SMT; Manufacturer: Hirose; ArticleNumber: 810-0346; Inventory Storage Name: L2; Inventory Storage Section: Kasten79; Inventory Storage Info: 11067; Sachgruppe: SV_HF_KOAXIAL; SachgruppeCode: HF, Koaxial; IsReviewed: 1; InternalPrice: 0,663333; InternalStock: 114; Gender: m; Winkel: 180°; Montage: SMD; Z: 50R
X4 = E2448B04-DC6E-4F04-8FE3-EBFE442A9048: CON2(1)[Stiftleiste][Jumper]; Manufacturer: Tyco Electronics; ArticleNumber: 810-0378; NAME: 825433-2; Inventory Storage Name: LBaut; Inventory Storage Section: X14; Sachgruppe: SV_STIFT_BUCHSENLEISTEN; SachgruppeCode: Stift-/Buchsenleisten; IsReviewed: 1; InternalPrice: 0,375; InternalStock: 338; Pole: 2; Gender: m; Winkel: 180°; Pitch: 2,54mm; I_max: 3A; Montage: THT; Kommentar: B2W

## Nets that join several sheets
1V8: Power (C22.2 U8.5), Laserdriver (C29.1 U7.8)
3V3: EVK75123-Illumination-FB (7 pins), Power (C19.2 U6.5)
5V0: EVK75123-Illumination-FB (C17.2 C50.2 L4.2 U3.1), Power (5 pins), Laserdriver (7 pins)
24V: EVK75123-Illumination-FB (5 pins), Power (C12.2 U5.2)
GND: EVK75123-Illumination-FB (17 pins), Power (22 pins), Laserdriver (34 pins)
VLD: Power (6 pins), Laserdriver (8 pins)
FB: EVK75123-Illumination-FB (X6.12), Laserdriver (C27.1 R20.2 R28.2 X2.2)
MOD_N: EVK75123-Illumination-FB (MOD-.1 X6.15), Laserdriver (R32.1 U1.14 U1.16 U1.20)
MOD_P: EVK75123-Illumination-FB (MOD+.1 X6.17), Laserdriver (R32.2 U1.15 U1.17 U1.21)
nERR: EVK75123-Illumination-FB (L5.1 R2.1), Laserdriver (U1.22)
PEN: EVK75123-Illumination-FB (U4.4), Power (R3.2 U5.3)
V_CI: EVK75123-Illumination-FB (U3.6), Laserdriver (R4.2)
V_DAC_C: EVK75123-Illumination-FB (U3.8), Laserdriver (R26.1)
VPROG: EVK75123-Illumination-FB (U3.7), Power (R19.2)

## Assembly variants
60° x 40°: not fitted V13_L V13_R V14_L V14_R V15_L V15_R V16_L V16_R V17_L V17_R V18_L V18_R V19_L V19_R V20_L V20_R
110°: not fitted V17_L V17_R V18_L V18_R V19_L V19_R V20_L V20_R; alternate parts V1_R -> 27129d98-1344-4fb2-a297-1e36a3f61028, V2_R -> 27129d98-1344-4fb2-a297-1e36a3f61028, V3_R -> 27129d98-1344-4fb2-a297-1e36a3f61028, V4_R -> 27129d98-1344-4fb2-a297-1e36a3f61028, V1_L -> 27129d98-1344-4fb2-a297-1e36a3f61028, V2_L -> 27129d98-1344-4fb2-a297-1e36a3f61028, V3_L -> 27129d98-1344-4fb2-a297-1e36a3f61028, V4_L -> 27129d98-1344-4fb2-a297-1e36a3f61028
19°: not fitted V13_L V13_R V14_L V14_R V15_L V15_R V16_L V16_R; alternate parts V4_L -> e9a740a4-88eb-4583-a0a4-5d5badcb96cd, V3_L -> e9a740a4-88eb-4583-a0a4-5d5badcb96cd, V2_L -> e9a740a4-88eb-4583-a0a4-5d5badcb96cd, V1_L -> e9a740a4-88eb-4583-a0a4-5d5badcb96cd, V4_R -> e9a740a4-88eb-4583-a0a4-5d5badcb96cd, V3_R -> e9a740a4-88eb-4583-a0a4-5d5badcb96cd, V2_R -> e9a740a4-88eb-4583-a0a4-5d5badcb96cd, V1_R -> e9a740a4-88eb-4583-a0a4-5d5badcb96cd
